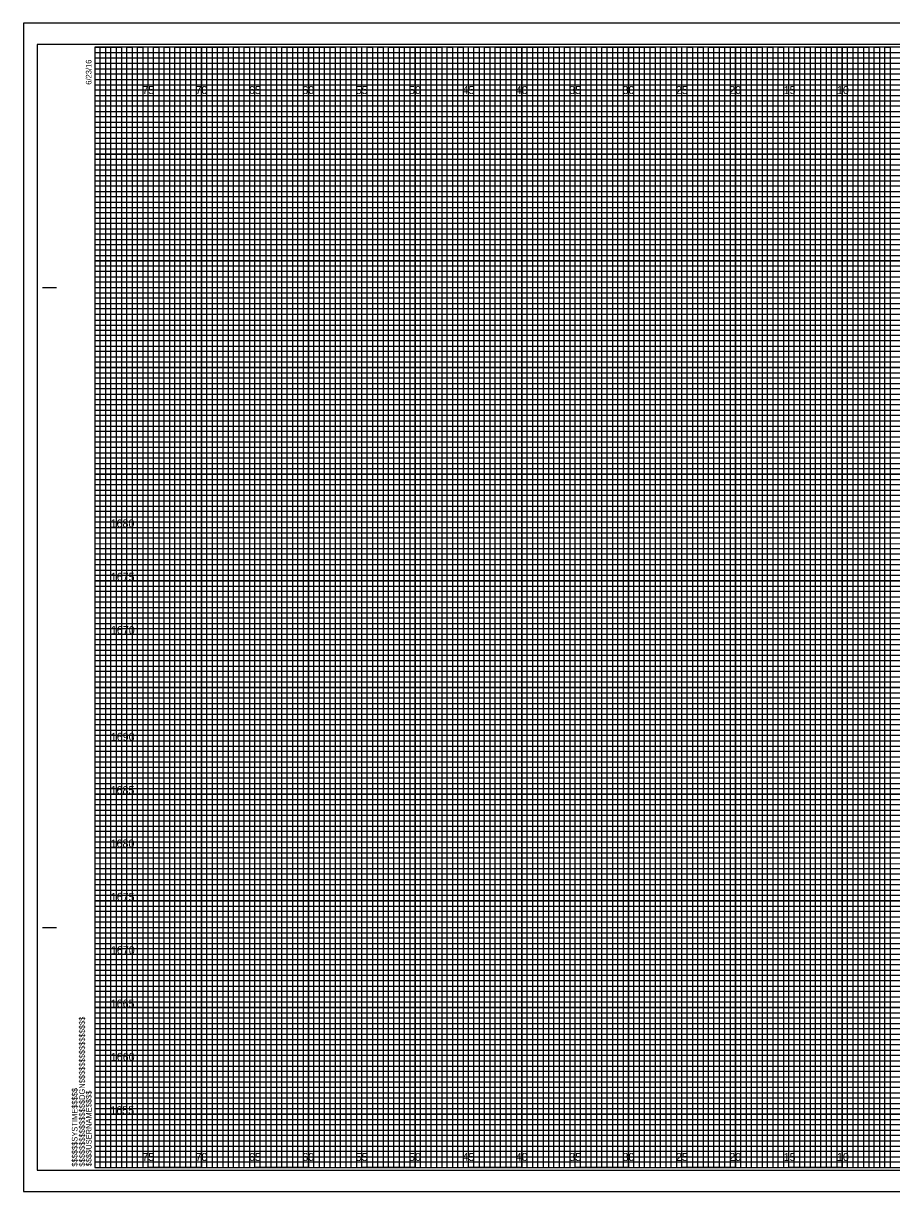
# Model space of a CAD drawing. Extents: x -73 to 95, y 6 to 446.
# Drawn here: x -73.1 to 8.2, y 336.1 to 445.6 of the extents above; entities that cross this region are included whole.
import ezdxf

# ---------------------------------------------------------------- set-up
doc = ezdxf.new("R2010")
doc.units = 0
for name, color, linetype in [('Exist CMT Alignment Centerline', 7, 'Continuous'), ('Prop Horizontal Alignment', 7, 'Continuous'), ('Prop XS DDE', 7, 'Continuous'), ('Raster_Level_0', 7, 'Continuous'), ('Sheet Cross Section CELL', 7, 'Continuous'), ('Sheet Cross Section Grid Minor 1 CELL', 7, 'Continuous'), ('Sheet Cross Section Grid Minor 2 CELL', 7, 'Continuous'), ('Sheet Cutting Line CELL', 7, 'Continuous'), ('Sheet DOT Grid CELL', 7, 'Continuous'), ('Sheet Plot Border Inside CELL', 7, 'Continuous'), ('Sheet Plot Border Outside CELL', 7, 'Continuous')]:
    doc.layers.add(name, color=color, linetype=linetype)

msp = doc.modelspace()

# ---------------------------------------------------------------- linework, layer by layer
at = {"layer": 'Exist CMT Alignment Centerline'}
for p, q in [((-61.4, 443.4), (-66.4, 443.4)), ((-61.4, 338.4), (-61.4, 443.4)), ((-51.4, 443.4), (-56.4, 443.4)), ((-56.4, 443.4), (-56.4, 338.4)), ((-51.4, 338.4), (-51.4, 443.4)), ((-41.4, 443.4), (-46.4, 443.4)), ((-46.4, 443.4), (-46.4, 338.4)), ((-41.4, 338.4), (-41.4, 443.4)), ((-31.4, 443.4), (-36.4, 443.4)), ((-36.4, 443.4), (-36.4, 338.4)), ((-31.4, 338.4), (-31.4, 443.4)), ((-21.4, 443.4), (-26.4, 443.4)), ((-26.4, 443.4), (-26.4, 338.4)), ((-21.4, 338.4), (-21.4, 443.4)), ((-11.4, 443.4), (-16.4, 443.4)), ((-16.4, 443.4), (-16.4, 338.4)), ((-11.4, 338.4), (-11.4, 443.4)), ((-1.4, 443.4), (-6.4, 443.4)), ((-6.4, 443.4), (-6.4, 338.4)), ((-1.4, 338.4), (-1.4, 443.4)), ((8.6, 443.4), (3.6, 443.4)), ((3.6, 443.4), (3.6, 338.4)), ((-56.4, 338.4), (-61.4, 338.4)), ((-46.4, 338.4), (-51.4, 338.4)), ((-36.4, 338.4), (-41.4, 338.4)), ((-26.4, 338.4), (-31.4, 338.4)), ((-16.4, 338.4), (-21.4, 338.4)), ((-6.4, 338.4), (-11.4, 338.4)), ((3.6, 338.4), (-1.4, 338.4))]:
    msp.add_line(p, q, dxfattribs=at)
for points in [[(-66.4, 438.4), (93.6, 438.4), (93.6, 433.4), (-66.4, 433.4)], [(-66.4, 428.4), (93.6, 428.4), (93.6, 423.4), (-66.4, 423.4)], [(-66.4, 418.4), (93.6, 418.4), (93.6, 413.4), (-66.4, 413.4)], [(-66.4, 408.4), (93.6, 408.4), (93.6, 403.4), (-66.4, 403.4)], [(-66.4, 398.4), (93.6, 398.4), (93.6, 393.4), (-66.4, 393.4)], [(-66.4, 388.4), (93.6, 388.4), (93.6, 383.4), (-66.4, 383.4)], [(-66.4, 378.4), (93.6, 378.4), (93.6, 373.4), (-66.4, 373.4)], [(-66.4, 368.4), (93.6, 368.4), (93.6, 363.4), (-66.4, 363.4)], [(-66.4, 358.4), (93.6, 358.4), (93.6, 353.4), (-66.4, 353.4)], [(-66.4, 348.4), (93.6, 348.4), (93.6, 343.4), (-66.4, 343.4)]]:
    msp.add_lwpolyline(points, dxfattribs=at)
at = {"layer": 'Prop XS DDE'}
for points in [[(-66.4, 443.4), (-63.9, 443.4), (-63.9, 338.4), (-58.9, 338.4), (-58.9, 443.4), (-53.9, 443.4), (-53.9, 338.4), (-48.9, 338.4), (-48.9, 443.4), (-43.9, 443.4), (-43.9, 338.4), (-38.9, 338.4), (-38.9, 443.4), (-33.9, 443.4), (-33.9, 338.4), (-28.9, 338.4), (-28.9, 443.4), (-23.9, 443.4), (-23.9, 338.4), (-18.9, 338.4), (-18.9, 443.4), (-13.9, 443.4), (-13.9, 338.4), (-8.9, 338.4), (-8.9, 443.4), (-3.9, 443.4), (-3.9, 338.4), (1.1, 338.4), (1.1, 443.4), (6.1, 443.4), (6.1, 338.4), (11.1, 338.4)], [(-66.4, 440.9), (71.1, 440.9)], [(-66.4, 430.9), (93.6, 430.9), (93.6, 435.9), (-66.4, 435.9)], [(-66.4, 420.9), (93.6, 420.9), (93.6, 425.9), (-66.4, 425.9)], [(-66.4, 410.9), (93.6, 410.9), (93.6, 415.9), (-66.4, 415.9)], [(-66.4, 400.9), (93.6, 400.9), (93.6, 405.9), (-66.4, 405.9)], [(-66.4, 390.9), (93.6, 390.9), (93.6, 395.9), (-66.4, 395.9)], [(-66.4, 380.9), (93.6, 380.9), (93.6, 385.9), (-66.4, 385.9)], [(-66.4, 370.9), (93.6, 370.9), (93.6, 375.9), (-66.4, 375.9)], [(-66.4, 360.9), (93.6, 360.9), (93.6, 365.9), (-66.4, 365.9)], [(-66.4, 350.9), (93.6, 350.9), (93.6, 355.9), (-66.4, 355.9)], [(-66.4, 340.9), (93.6, 340.9), (93.6, 345.9), (-66.4, 345.9)]]:
    msp.add_lwpolyline(points, dxfattribs=at)
at = {"layer": 'Sheet Cross Section CELL'}
for p, q in [((-71.3, 420.9), (-70.05, 420.9)), ((-71.25, 420.9), (-70, 420.9)), ((-71.3, 360.9), (-70.05, 360.9)), ((-71.25, 360.9), (-70, 360.9)), ((-66.4, 338.4), (-66.4, 338.4)), ((-66.4, 338.4), (-66.4, 338.4)), ((-66.4, 338.4), (-66.4, 338.4)), ((-66.4, 338.4), (-66.4, 338.4)), ((-66.4, 338.4), (-66.4, 338.4)), ((-66.4, 338.4), (-66.4, 338.4)), ((-66.4, 338.4), (-66.4, 338.4))]:
    msp.add_line(p, q, dxfattribs=at)
msp.add_lwpolyline([(93.6, 443.4), (-66.4, 443.4), (-66.4, 338.4), (93.6, 338.4)], close=True, dxfattribs=at)
at = {"layer": 'Sheet Cross Section Grid Minor 1 CELL'}
for p, q in [((-66.4, 442.9), (63.6, 442.9)), ((63.6, 442.39), (-66.4, 442.39)), ((-66.4, 442.39), (-66.4, 441.9)), ((-66.4, 441.9), (63.6, 441.9)), ((63.6, 441.34), (-66.4, 441.34)), ((-66.4, 441.34), (-66.4, 440.4)), ((-66.4, 440.4), (93.6, 440.4))]:
    msp.add_line(p, q, dxfattribs=at)
for points in [[(-66.4, 439.9), (68.6, 439.9), (93.6, 439.9), (93.6, 439.4), (-66.4, 439.4)], [(-66.4, 438.9), (93.6, 438.9), (93.6, 437.9), (-66.4, 437.9)], [(-66.4, 437.4), (93.6, 437.4), (93.6, 436.9), (-66.4, 436.89)], [(-66.4, 436.4), (93.6, 436.4), (93.6, 435.4), (-66.4, 435.4)], [(-66.4, 434.9), (93.6, 434.9), (93.6, 434.4), (-66.4, 434.4)], [(-66.4, 433.9), (93.6, 433.9), (93.6, 432.9), (-66.4, 432.9)], [(-66.4, 432.4), (93.6, 432.4), (93.6, 431.9), (-66.4, 431.9)], [(-66.4, 431.4), (93.6, 431.4), (93.6, 430.4), (-66.4, 430.4)], [(-66.4, 429.9), (93.6, 429.9), (93.6, 429.4), (-66.4, 429.4)], [(-66.4, 428.9), (93.6, 428.9), (93.6, 427.9), (-66.4, 427.9)], [(-66.4, 427.4), (93.6, 427.4), (93.6, 426.9), (-66.4, 426.9)], [(-66.4, 426.4), (93.6, 426.4), (93.6, 425.37), (93.6, 424.9), (93.6, 424.4), (-66.4, 424.4)], [(-66.4, 425.4), (93.6, 425.4), (93.6, 424.9), (-66.4, 424.9)], [(-66.4, 423.9), (93.6, 423.9), (93.6, 422.9), (-66.4, 422.91)], [(-66.4, 422.91), (93.6, 422.9), (93.6, 422.4), (-66.4, 422.4)], [(-66.4, 421.9), (93.6, 421.9), (93.6, 421.4), (-66.4, 421.4)], [(-66.4, 420.4), (93.6, 420.4), (93.6, 419.9), (-66.4, 419.9)], [(-66.4, 419.4), (93.6, 419.4), (93.6, 418.9), (-66.4, 418.9)], [(-66.43, 417.84), (93.6, 417.84), (93.6, 417.34), (-66.43, 417.34)], [(-66.4, 416.9), (93.6, 416.9), (93.6, 416.4), (-66.4, 416.4)], [(-66.4, 415.4), (93.6, 415.4), (93.6, 414.9), (-66.4, 414.9)], [(-66.4, 414.4), (93.6, 414.4), (93.6, 413.9), (-66.4, 413.9)], [(-66.4, 412.9), (93.6, 412.9), (93.6, 412.4), (-66.4, 412.4)], [(-66.4, 411.9), (93.6, 411.9), (93.6, 411.4), (-66.4, 411.4)], [(-66.4, 410.4), (93.6, 410.4), (93.6, 409.9), (-66.4, 409.9)], [(-66.4, 409.4), (93.6, 409.4), (93.6, 408.9), (-66.4, 408.9)], [(-66.4, 407.9), (93.6, 407.9), (93.6, 407.39), (-66.4, 407.4)], [(-66.4, 406.9), (93.6, 406.9), (93.6, 406.4), (-66.4, 406.4)], [(-66.4, 405.4), (93.6, 405.4), (93.6, 404.9), (-66.4, 404.9)], [(-66.4, 404.4), (93.6, 404.4), (93.6, 403.9), (-66.4, 403.9)], [(-66.4, 402.9), (93.6, 402.9), (93.6, 402.4), (-66.4, 402.4)], [(-66.4, 401.9), (93.6, 401.9), (93.6, 401.4), (-66.4, 401.4)], [(-66.4, 400.4), (93.6, 400.4), (93.6, 399.9), (-66.4, 399.9)], [(-66.4, 399.4), (93.6, 399.4), (93.6, 398.9), (-66.4, 398.9)], [(-66.4, 397.9), (93.6, 397.9), (93.6, 397.4), (-66.4, 397.4)], [(-66.4, 396.89), (93.64, 396.85), (93.6, 396.4), (-66.4, 396.4)], [(-66.4, 395.4), (93.6, 395.4), (93.6, 394.9), (-66.4, 394.9)], [(-66.4, 394.4), (93.6, 394.4), (93.6, 393.9), (-66.4, 393.9)], [(-66.4, 392.9), (93.6, 392.9), (93.6, 392.4), (-66.4, 392.4)], [(-66.4, 391.9), (93.6, 391.9), (93.6, 391.4), (-66.4, 391.4)], [(-66.4, 390.4), (93.6, 390.4), (93.6, 389.9), (-66.4, 389.9)], [(-66.4, 389.4), (93.6, 389.4), (93.6, 388.9), (-66.4, 388.9)], [(-66.4, 387.9), (93.6, 387.9), (93.6, 387.4), (-66.4, 387.4)], [(-66.4, 386.9), (93.6, 386.9), (93.6, 386.4), (-66.4, 386.4)], [(-66.4, 385.4), (93.6, 385.4), (93.6, 384.9), (-66.4, 384.9)], [(-66.4, 384.4), (93.6, 384.4), (93.6, 383.9), (-66.4, 383.9)], [(-66.4, 382.9), (93.6, 382.9), (93.6, 382.4), (-66.4, 382.4)], [(-66.4, 381.9), (93.6, 381.9), (93.6, 381.4), (-66.4, 381.4)], [(-66.4, 380.4), (93.6, 380.4), (93.6, 379.9), (-66.4, 379.9)], [(-66.4, 379.4), (93.6, 379.4), (93.6, 378.9), (-66.4, 378.9)], [(-66.4, 377.9), (93.6, 377.9), (93.6, 377.39), (-66.4, 377.4)], [(-66.4, 376.9), (93.6, 376.9), (93.6, 376.4), (-66.4, 376.4)], [(-66.4, 375.4), (93.6, 375.4), (93.6, 374.9), (-66.4, 374.9)], [(-66.4, 374.4), (93.6, 374.4), (93.6, 373.9), (-66.4, 373.9)], [(-66.4, 372.9), (93.6, 372.9), (93.6, 372.4), (-66.4, 372.4)], [(-66.4, 371.9), (93.6, 371.9), (93.6, 371.4), (-66.4, 371.4)], [(-66.4, 370.4), (93.6, 370.4), (93.6, 369.9), (-66.4, 369.9)], [(-66.4, 369.4), (93.6, 369.4), (93.6, 368.9), (-66.4, 368.9)], [(-66.4, 367.9), (93.6, 367.9), (93.6, 367.4), (-66.4, 367.4)], [(-66.4, 366.89), (93.64, 366.85), (93.6, 366.4), (-66.4, 366.4)], [(-66.4, 365.4), (93.6, 365.4), (93.6, 364.9), (-66.4, 364.9)], [(-66.4, 364.4), (93.6, 364.4), (93.6, 363.9), (-66.4, 363.9)], [(-66.4, 362.9), (93.6, 362.9), (93.6, 362.4), (-66.4, 362.4)], [(-66.4, 361.9), (93.6, 361.9), (93.6, 361.4), (-66.4, 361.4)], [(-66.4, 360.4), (93.6, 360.4), (93.6, 359.9), (-66.4, 359.9)], [(-66.4, 359.4), (93.6, 359.4), (93.6, 358.9), (-66.4, 358.9)], [(-66.4, 357.9), (93.6, 357.9), (93.6, 357.4), (-66.4, 357.4)], [(-66.4, 356.9), (93.6, 356.9), (93.6, 356.4), (-66.4, 356.4)], [(-66.4, 355.4), (93.6, 355.4), (93.6, 354.9), (-66.4, 354.9)], [(-66.4, 354.4), (93.6, 354.4), (93.6, 353.9), (-66.4, 353.9)], [(-66.4, 352.9), (93.6, 352.9), (93.6, 352.4), (-66.4, 352.4)], [(-66.4, 351.9), (93.6, 351.9), (93.6, 351.4), (-66.4, 351.4)], [(-66.4, 350.4), (93.6, 350.4), (93.6, 349.9), (-66.4, 349.9)], [(-66.4, 349.4), (93.6, 349.4), (93.6, 348.9), (-66.4, 348.9)], [(-66.4, 347.9), (93.6, 347.9), (93.6, 347.4), (-66.4, 347.4)], [(-66.4, 346.9), (93.6, 346.9), (93.6, 346.4), (-66.4, 346.4)], [(-66.4, 345.4), (93.6, 345.4), (93.6, 344.9), (-66.4, 344.9)], [(-66.4, 344.4), (93.6, 344.4), (93.6, 343.9), (-66.4, 343.9)], [(-66.4, 342.9), (93.6, 342.9), (93.6, 342.4), (-66.4, 342.4)], [(-66.4, 341.9), (93.6, 341.9), (93.6, 341.4), (-66.4, 341.4)], [(-66.4, 340.4), (93.6, 340.4), (93.6, 339.9), (-66.4, 339.9)], [(-66.4, 339.4), (93.6, 339.4), (93.6, 338.9), (-66.4, 338.9)]]:
    msp.add_lwpolyline(points, dxfattribs=at)
at = {"layer": 'Sheet Cross Section Grid Minor 2 CELL'}
for points in [[(-66.4, 338.4), (-65.9, 338.4), (-65.9, 443.4), (-65.4, 443.4), (-65.4, 338.4)], [(-65.4, 338.4), (-64.9, 338.4), (-64.9, 443.4), (-64.4, 443.4), (-64.4, 338.4)], [(-63.9, 338.4), (-63.4, 338.4), (-63.4, 443.4), (-62.9, 443.4), (-62.9, 338.4)], [(-62.9, 338.4), (-62.4, 338.4), (-62.4, 443.4), (-61.9, 443.4), (-61.9, 338.4)], [(-61.4, 338.4), (-60.9, 338.4), (-60.9, 443.4), (-60.4, 443.4), (-60.4, 338.4)], [(-60.4, 338.4), (-59.9, 338.4), (-59.9, 443.4), (-59.4, 443.4), (-59.4, 338.4)], [(-58.9, 338.4), (-58.4, 338.4), (-58.4, 443.4), (-57.9, 443.4), (-57.9, 338.4)], [(-57.9, 338.4), (-57.4, 338.4), (-57.4, 443.4), (-56.9, 443.4), (-56.9, 338.4)], [(-56.4, 338.4), (-55.9, 338.4), (-55.9, 443.4), (-55.4, 443.4), (-55.4, 338.4)], [(-55.4, 338.4), (-54.9, 338.4), (-54.9, 443.4), (-54.4, 443.4), (-54.4, 338.4)], [(-53.9, 338.4), (-53.4, 338.4), (-53.4, 443.4), (-52.9, 443.4), (-52.9, 338.4)], [(-52.9, 338.4), (-52.4, 338.4), (-52.4, 443.4), (-51.9, 443.4), (-51.9, 338.4)], [(-51.4, 338.4), (-50.9, 338.4), (-50.9, 443.4), (-50.4, 443.4), (-50.4, 338.4)], [(-50.4, 338.4), (-49.9, 338.4), (-49.9, 443.4), (-49.4, 443.4), (-49.4, 338.4)], [(-48.9, 338.4), (-48.4, 338.4), (-48.4, 443.4), (-47.9, 443.4), (-47.9, 338.4)], [(-47.9, 338.4), (-47.4, 338.4), (-47.4, 443.4), (-46.9, 443.4), (-46.9, 338.4)], [(-46.4, 338.4), (-45.9, 338.4), (-45.9, 443.4), (-45.4, 443.4), (-45.4, 338.4)], [(-45.4, 338.4), (-44.9, 338.4), (-44.9, 443.4), (-44.4, 443.4), (-44.4, 338.4)], [(-43.9, 338.4), (-43.4, 338.4), (-43.4, 443.4), (-42.9, 443.4), (-42.9, 338.4)], [(-42.9, 338.4), (-42.4, 338.4), (-42.4, 443.4), (-41.9, 443.4), (-41.9, 338.4)], [(-41.4, 338.4), (-40.9, 338.4), (-40.9, 443.4), (-40.4, 443.4), (-40.4, 338.4)], [(-40.4, 338.4), (-39.9, 338.4), (-39.9, 443.4), (-39.4, 443.4), (-39.4, 338.4)], [(-38.9, 338.4), (-38.4, 338.4), (-38.4, 443.4), (-37.9, 443.4), (-37.9, 338.4)], [(-37.9, 338.4), (-37.4, 338.4), (-37.4, 443.4), (-36.9, 443.4), (-36.9, 338.4)], [(-36.4, 338.4), (-35.9, 338.4), (-35.9, 443.4), (-35.4, 443.4), (-35.4, 338.4)], [(-35.4, 338.4), (-34.9, 338.4), (-34.9, 443.4), (-34.4, 443.4), (-34.4, 338.4)], [(-33.9, 338.4), (-33.4, 338.4), (-33.4, 443.4), (-32.9, 443.4), (-32.9, 338.4)], [(-32.9, 338.4), (-32.4, 338.4), (-32.4, 443.4), (-31.9, 443.4), (-31.9, 338.4)], [(-31.4, 338.4), (-30.9, 338.4), (-30.9, 443.4), (-30.4, 443.4), (-30.4, 338.4)], [(-30.4, 338.4), (-29.9, 338.4), (-29.9, 443.4), (-29.4, 443.4), (-29.4, 338.4)], [(-28.9, 338.4), (-28.4, 338.4), (-28.4, 443.4), (-27.9, 443.4), (-27.9, 338.4)], [(-27.9, 338.4), (-27.4, 338.4), (-27.4, 443.4), (-26.9, 443.4), (-26.9, 338.4)], [(-26.4, 338.4), (-25.9, 338.4), (-25.9, 443.4), (-25.4, 443.4), (-25.4, 338.4)], [(-25.4, 338.4), (-24.9, 338.4), (-24.9, 443.4), (-24.4, 443.4), (-24.4, 338.4)], [(-23.9, 338.4), (-23.4, 338.4), (-23.4, 443.4), (-22.9, 443.4), (-22.9, 338.4)], [(-22.9, 338.4), (-22.4, 338.4), (-22.4, 443.4), (-21.9, 443.4), (-21.9, 338.4)], [(-21.4, 338.4), (-20.9, 338.4), (-20.9, 443.4), (-20.4, 443.4), (-20.4, 338.4)], [(-20.4, 338.4), (-19.9, 338.4), (-19.9, 443.4), (-19.4, 443.4), (-19.4, 338.4)], [(-18.9, 338.4), (-18.4, 338.4), (-18.4, 443.4), (-17.9, 443.4), (-17.9, 338.4)], [(-17.9, 338.4), (-17.4, 338.4), (-17.4, 443.4), (-16.9, 443.4), (-16.9, 338.4)], [(-16.4, 338.4), (-15.9, 338.4), (-15.9, 443.4), (-15.4, 443.4), (-15.4, 338.4)], [(-15.4, 338.4), (-14.9, 338.4), (-14.9, 443.4), (-14.4, 443.4), (-14.4, 338.4)], [(-13.9, 338.4), (-13.4, 338.4), (-13.4, 443.4), (-12.9, 443.4), (-12.9, 338.4)], [(-12.9, 338.4), (-12.4, 338.4), (-12.4, 443.4), (-11.9, 443.4), (-11.9, 338.4)], [(-11.4, 338.4), (-10.9, 338.4), (-10.9, 443.4), (-10.4, 443.4), (-10.4, 338.4)], [(-10.4, 338.4), (-9.9, 338.4), (-9.9, 443.4), (-9.4, 443.4), (-9.4, 338.4)], [(-8.9, 338.4), (-8.4, 338.4), (-8.4, 443.4), (-7.9, 443.4), (-7.9, 338.4)], [(-7.9, 338.4), (-7.4, 338.4), (-7.4, 443.4), (-6.9, 443.4), (-6.9, 338.4)], [(-6.4, 338.4), (-5.9, 338.4), (-5.9, 443.4), (-5.4, 443.4), (-5.4, 338.4)], [(-5.4, 338.4), (-4.9, 338.4), (-4.9, 443.4), (-4.4, 443.4), (-4.4, 338.4)], [(-3.9, 338.4), (-3.4, 338.4), (-3.4, 443.4), (-2.9, 443.4), (-2.9, 338.4)], [(-2.9, 338.4), (-2.4, 338.4), (-2.4, 443.4), (-1.9, 443.4), (-1.9, 338.4)], [(-1.4, 338.4), (-0.9, 338.4), (-0.9, 443.4), (-0.4, 443.4), (-0.4, 338.4)], [(-0.4, 338.4), (0.1, 338.4), (0.1, 443.4), (0.6, 443.4), (0.6, 338.4)], [(1.1, 338.4), (1.6, 338.4), (1.6, 443.4), (2.1, 443.4), (2.1, 338.4)], [(2.1, 338.4), (2.6, 338.4), (2.6, 443.4), (3.1, 443.4), (3.1, 338.4)], [(3.6, 338.4), (4.1, 338.4), (4.1, 443.4), (4.6, 443.4), (4.6, 338.4)], [(4.6, 338.4), (5.1, 338.4), (5.1, 443.4), (5.6, 443.4), (5.6, 338.4)], [(6.1, 338.4), (6.6, 338.4), (6.6, 443.4), (7.1, 443.4), (7.1, 338.4)], [(7.1, 338.4), (7.6, 338.4), (7.6, 443.4), (8.1, 443.4), (8.1, 338.4)]]:
    msp.add_lwpolyline(points, dxfattribs=at)
at = {"layer": 'Sheet Cutting Line CELL'}
for p, q in [((95.25, 445.65), (-73.1, 445.65)), ((-73.1, 445.65), (-73.1, 336.15)), ((-73.1, 336.15), (95.25, 336.15))]:
    msp.add_line(p, q, dxfattribs=at)
at = {"layer": 'Sheet DOT Grid CELL'}
for p, q in [((-61.4, 338.4), (-61.4, 443.4)), ((-56.4, 338.4), (-56.4, 443.4)), ((-51.4, 338.4), (-51.4, 443.4)), ((-46.4, 338.4), (-46.4, 443.4)), ((-41.4, 338.4), (-41.4, 443.4)), ((-36.4, 338.4), (-36.4, 443.4)), ((-31.4, 338.4), (-31.4, 443.4)), ((-26.4, 338.4), (-26.4, 443.4)), ((-21.4, 338.4), (-21.4, 443.4)), ((-16.4, 338.4), (-16.4, 443.4)), ((-11.4, 338.4), (-11.4, 443.4)), ((-6.4, 338.4), (-6.4, 443.4)), ((-1.4, 338.4), (-1.4, 443.4)), ((3.6, 338.4), (3.6, 443.4)), ((-66.4, 438.4), (93.6, 438.4)), ((-66.4, 433.4), (93.6, 433.4)), ((-66.4, 428.4), (93.6, 428.4)), ((-66.4, 423.4), (93.6, 423.4)), ((-66.4, 418.4), (93.6, 418.4)), ((-66.4, 413.4), (93.6, 413.4)), ((-66.4, 408.4), (93.6, 408.4)), ((-66.4, 403.4), (93.6, 403.4)), ((-66.4, 398.4), (93.6, 398.4)), ((-66.4, 393.4), (93.6, 393.4)), ((-66.4, 388.4), (93.6, 388.4)), ((-66.4, 383.4), (93.6, 383.4)), ((-66.4, 378.4), (93.6, 378.4)), ((-66.4, 373.4), (93.6, 373.4)), ((-66.4, 368.4), (93.6, 368.4)), ((-66.4, 363.4), (93.6, 363.4)), ((-66.4, 358.4), (93.6, 358.4)), ((-66.4, 353.4), (93.6, 353.4)), ((-66.4, 348.4), (93.6, 348.4)), ((-66.4, 343.4), (93.6, 343.4))]:
    msp.add_line(p, q, dxfattribs=at)
at = {"layer": 'Sheet Plot Border Inside CELL'}
msp.add_lwpolyline([(-71.8, 338.15), (94.8, 338.15), (94.8, 443.65), (-71.8, 443.65)], close=True, dxfattribs=at)
at = {"layer": 'Sheet Plot Border Outside CELL'}
msp.add_lwpolyline([(-73.1, 336.15), (95.25, 336.15), (95.25, 445.65), (-73.1, 445.65)], close=True, dxfattribs=at)

# ---------------------------------------------------------------- texts
at = {"layer": 'Prop Horizontal Alignment'}
for s, p in [('1680', (-64.93, 398.4)), ('1675', (-64.91, 393.4)), ('1670', (-64.9, 388.4)), ('1690', (-64.91, 378.4)), ('1685', (-64.93, 373.4)), ('1680', (-64.93, 368.4)), ('1675', (-64.91, 363.4)), ('1670', (-64.9, 358.4)), ('1665', (-64.92, 353.4)), ('1660', (-64.91, 348.4)), ('1655', (-64.95, 343.4))]:
    msp.add_text(s, height=0.75, dxfattribs=at).set_placement(p)
at = {"layer": 'Raster_Level_0'}
for s, p in [('75', (-61.96, 439.02)), ('70', (-56.97, 439.02)), ('65', (-51.96, 439.02)), ('60', (-46.97, 439.02)), ('55', (-41.96, 439.02)), ('50', (-36.97, 439.02)), ('45', (-31.96, 439.02)), ('40', (-26.97, 439.02)), ('35', (-21.96, 439.02)), ('30', (-16.97, 439.02)), ('25', (-11.96, 439.02)), ('20', (-6.97, 439.02)), ('15', (-1.87, 439.02)), ('10', (3.12, 439.02)), ('75', (-61.96, 339.02)), ('70', (-56.97, 339.02)), ('65', (-51.96, 339.02)), ('60', (-46.97, 339.02)), ('55', (-41.96, 339.02)), ('50', (-36.97, 339.02)), ('45', (-31.96, 339.02)), ('40', (-26.97, 339.02)), ('35', (-21.96, 339.02)), ('30', (-16.97, 339.02)), ('25', (-11.96, 339.02)), ('20', (-6.97, 339.02)), ('15', (-1.87, 339.02)), ('10', (3.12, 339.02))]:
    msp.add_text(s, height=0.75, dxfattribs=at).set_placement(p)
at = {"layer": 'Sheet Cross Section CELL'}
for s, p in [('6/23/16', (-66.72, 439.9)), ('$$$$$$$$$$$$$$$$DGN$$$$$$$$$$$$$$$$', (-67.34, 338.49)), ('$$$$$$SYSTIME$$$$$', (-68.03, 338.49)), ('$$$$USERNAME$$$$', (-66.71, 338.51))]:
    msp.add_text(s, height=0.525, rotation=90, dxfattribs=at).set_placement(p)

doc.saveas('drawing.dxf')
